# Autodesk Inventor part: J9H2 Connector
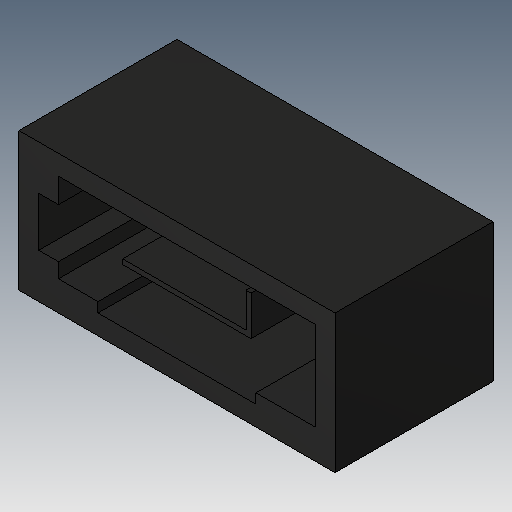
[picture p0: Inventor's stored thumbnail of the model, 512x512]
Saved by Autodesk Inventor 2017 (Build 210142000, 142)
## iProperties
Created: 2005-12
Part Number: J9H2 Connector
Material: Generic
Document SubType Name: Modeling
Designer: DanielSeverino
Density: 1 g/cm^3
Appearance: Default
Author: DanielSeverino
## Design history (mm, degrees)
feature "Solid1"
body "Solid2"
